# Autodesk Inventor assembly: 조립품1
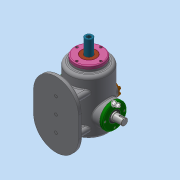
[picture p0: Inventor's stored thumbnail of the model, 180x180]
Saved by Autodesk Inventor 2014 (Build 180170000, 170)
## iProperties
Created: 2022-08
Part Number: 조립품1
Document SubType Name: Assembly
Designer: dg
Author: dg
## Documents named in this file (16)
- C:\Users\dg\Desktop\620806V1006\조립품1.iam
- C:\Users\dg\Desktop\620806V1006\본체.ipt
- C:\Users\dg\Desktop\620806V1006\베어링 6205.ipt
- 베어링 6205.ipt
- C:\Users\dg\Desktop\620806V1006\볼트 M4x0.7.ipt
- C:\Users\dg\Desktop\620806V1006\부시.ipt
- C:\Users\dg\Desktop\620806V1006\상부 캡.ipt
- C:\Users\dg\Desktop\620806V1006\슬라이드 커버.ipt
- C:\Users\dg\Desktop\620806V1006\슬라이드.ipt
- C:\Users\dg\Desktop\620806V1006\오일실.ipt
- 오일실.ipt
- C:\Users\dg\Desktop\620806V1006\축 커버-1.ipt
- C:\Users\dg\Desktop\620806V1006\축 커버-2.ipt
- C:\Users\dg\Desktop\620806V1006\편심축.ipt
- C:\Users\dg\Desktop\620806V1006\플레이트.ipt
- C:\Users\dg\Desktop\620806V1006\가변스프링.ipt
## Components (14 placed, 3 different names)
1. M4x0.7:1
2. 플레이트:1
3. M4x0.7:2
4. M4x0.7:3
5. M4x0.7:4
6. M4x0.7:5
7. M4x0.7:6
8. M4x0.7:7
9. M4x0.7:8
10. M4x0.7:9
11. M4x0.7:10
12. M4x0.7:11
13. M4x0.7:12
14. 가변스프링:1
